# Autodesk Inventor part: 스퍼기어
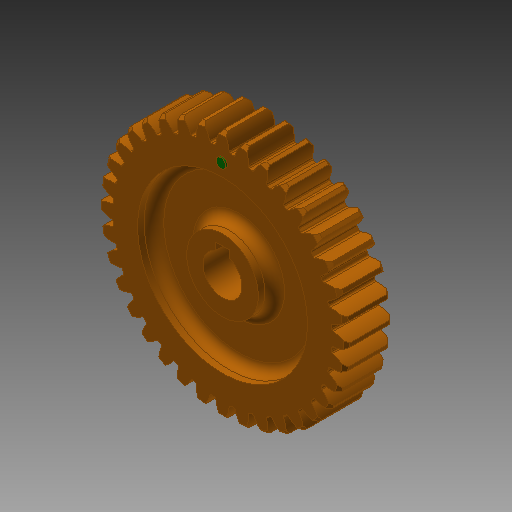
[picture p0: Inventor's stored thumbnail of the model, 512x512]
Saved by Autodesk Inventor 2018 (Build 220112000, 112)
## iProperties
Created: 2019-01
Part Number: 스퍼기어
Material: 알루미늄 6061
Document SubType Name: Modeling
Designer: mduedu
Density: 2.71 g/cm^3
Appearance: 주황색
Mass: 108.18 g
Surface Area: 169.519 cm^2
Volume: 39.919 cm^3
Author: mduedu
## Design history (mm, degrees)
sketch "스케치1"
  geometry: C1 r 33.5 at (0, 0); C2 r 36 at (0, 0); C3 r 38 at (0, 0); 1 further point
  constraints: 3 centre point, 3 coincident
  dimensions: "d0" = 67 diameter of C1; "d2" = 72 diameter of C2; "d3" = 76 diameter of C3
extrude "돌출1" new body sketch "스케치1" distance "d4" = 14; taper "d5" = 0 deg
sketch "스케치2"
  geometry: L1 (0, 0)-(-38, 0); L2 (0, 0)-(0, 38); L3 (-0.57, 0)-(-0.57, 37.996); L4 (-1.57, 0)-(-1.57, 35.966); L5 (-2.07, 0)-(-2.07, 33.436); A1 r 38 centre (0, 0) between (-38, 0) and (0, 38) reference; A2 r 9.246 centre (7.162, 32.926) between (-0.57, 37.996) and (-2.07, 33.436); A3 r 9.246 centre (-7.162, 32.926) between (2.07, 33.436) and (0.57, 37.996); A4 r 33.5 centre (0, 0) between (2.07, 33.436) and (-2.07, 33.436); A5 r 38 centre (0, 0) between (0.57, 37.996) and (-0.57, 37.996); 2 further points
  constraints: 12 point on circle, 10 end point, 4 centre point, 3 parallel, 3 symmetric about line, 2 coincident, 1 horizontal, 1 perpendicular, 5 other
  dimensions: "d6" = 0.5 distance between parallel lines of L4 L5; "d8" = 1 distance between parallel lines of L3 L4; "d9" = 1.57 distance between parallel lines of L2 L4
extrude "돌출2" join sketch "스케치2" stored distance "d10" = 14; taper "d11" = 0 deg
chamfer "모따기1" distance "d12" = 1; stored, may be unused: second distance "d13" = 2, angle "d14" = 45 deg
fillet "모깎기1" dims "d15" = 0.5
sketch "스케치3"
  geometry: C1 r 11 at (0, 0); 1 further point
  constraints: 1 centre point, 1 coincident
  dimensions: "d19" = 22 diameter of C1
extrude "돌출3" join sketch "스케치3" distance "d20" = 7; taper "d21" = 0 deg
sketch "스케치4"
  geometry: C1 r 11 at (0, 0); C2 r 26 at (0, 0); 1 further point
  constraints: 2 centre point, 2 coincident
  dimensions: "d23" = 22 diameter of C1; "d24" = 52 diameter of C2
extrude "돌출4" cut sketch "스케치4" distance "d25" = 5; taper "d26" = 0 deg
fillet "모깎기3" dims "d27" = 3
node "작업 평면1"
sketch "스케치5" dims "d28" = 60
  geometry: C1 r 1.5 at (0, 30); 2 further points
  constraints: 2 vertical alignment, 1 centre point, 1 coincident, 2 other
  dimensions: "d29" = 3 diameter of C1
extrude "돌출5" join sketch "스케치5" distance "d30" = 0.5; taper "d31" = 0 deg
sketch "스케치6"
  geometry: L1 (-2, 5.657)-(2, 5.657); L2 (2, 5.657)-(2, 7.8); L3 (2, 7.8)-(-2, 7.8); L4 (-2, 7.8)-(-2, 5.657); A1 r 6 centre (0, 0) between (-2, 5.657) and (2, 5.657); 1 further point
  constraints: 8 end point, 2 parallel, 2 point on circle, 1 centre point, 1 coincident, 1 horizontal, 1 perpendicular
  dimensions: "d32" = 13.8 dimension on A1 L3; "d34" = 4 distance of L2.end L3.end; "d35" = 12 diameter of A1
extrude "돌출6" cut sketch "스케치6" extent not by distance; stored distance "d36" = 0.5; taper "d37" = 0 deg
chamfer "모따기2" distance "d38" = 1; stored, may be unused: second distance "d39" = 2, angle "d40" = 45 deg
node "솔리드1"
pattern_circular "원형 패턴1" dims angle "d17" = 360 deg
mirror "대칭1"
